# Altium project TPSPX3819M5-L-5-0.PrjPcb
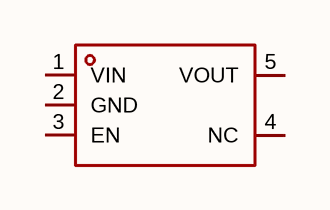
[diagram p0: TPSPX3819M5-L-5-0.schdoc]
1 sheet, 1 parts. Net scope: global (net labels, ports and power ports of the same name join across sheets).

## Sheet TPSPX3819M5-L-5-0.schdoc
size 127 x 101 mm

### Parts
U?  tpspx3819m5-l-5-0  [SOT-23-5_L2.9-W1.6-P0.95-LS2.8-BR]  (value not drawn)

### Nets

Not connected (* = marked no-connect by the designer): U? 1(VIN) 2(GND) 3(EN) 4(NC) 5(VOUT)

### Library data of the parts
U? = tpspx3819m5-l-5-0: 输出极性:正极;工作电压:20V;输出电压:5V;输出电流:500mA;电源纹波抑制比(PSRR):70dB@(1kHz);输出类型:固定;; Manufacturer: TECH PUBLIC(台舟); AddInBom: yes; ModelId: 7ba65df16e7b4570af156e925f9c37fe; ModelTransform: 114.173,114.173,0,90,0,0,0,0,0; Output Configuration: 正极; Voltage - Supply: 20V; Output Voltage: 5V; Output Current: 500mA; Voltage Dropout: 350mV@(100mA); standby current: 5uA; Output Type: 固定; Number of Outputs: 1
